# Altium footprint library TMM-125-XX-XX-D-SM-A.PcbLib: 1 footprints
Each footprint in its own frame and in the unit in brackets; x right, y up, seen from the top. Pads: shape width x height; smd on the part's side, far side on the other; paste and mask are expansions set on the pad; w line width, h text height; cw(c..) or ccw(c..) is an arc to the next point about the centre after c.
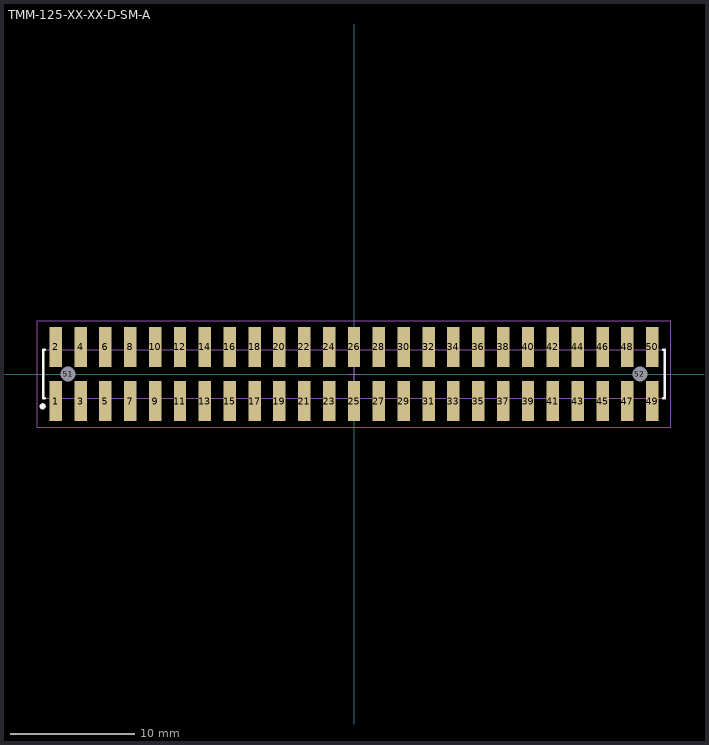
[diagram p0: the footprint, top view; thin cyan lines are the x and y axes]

## TMM-125-XX-XX-D-SM-A [mm] "2.00mm pitch, 50 pin, terminal strip; double row, w/alignment pins, SMT"
height 2.77
pads (52):
  rect 1x3.2 smd mask+0: 1(-24,-2.178) 2(-24,2.178) 3(-22,-2.178) 4(-22,2.178) 5(-20,-2.178) 6(-20,2.178) 7(-18,-2.178) 8(-18,2.178) 9(-16,-2.178) 10(-16,2.178) 11(-14,-2.178) 12(-14,2.178) 13(-12,-2.178) 14(-12,2.178) 15(-10,-2.178) 16(-10,2.178) 17(-8,-2.178) 18(-8,2.178) 19(-6,-2.178) 20(-6,2.178) 21(-4,-2.178) 22(-4,2.178) 23(-2,-2.178) 24(-2,2.178) 25(0,-2.178) 26(0,2.178) 27(2,-2.178) 28(2,2.178) 29(4,-2.178) 30(4,2.178) 31(6,-2.178) 32(6,2.178) 33(8,-2.178) 34(8,2.178) 35(10,-2.178) 36(10,2.178) 37(12,-2.178) 38(12,2.178) 39(14,-2.178) 40(14,2.178) 41(16,-2.178) 42(16,2.178) 43(18,-2.178) 44(18,2.178) 45(20,-2.178) 46(20,2.178) 47(22,-2.178) 48(22,2.178) 49(24,-2.178) 50(24,2.178)
  round 1 hole 1.2 unplated mask+0: 51(-23.006,0) 52(23.006,0)
Top Overlay:
  circle w0.25: c-25.05,-2.6 r0.125
  lines w0.2: -24.9,-1.95 -25,-1.95 -25,1.95 -24.9,1.95 ; 24.9,-1.95 25,-1.95 25,1.95 24.9,1.95
Mechanical 12:
  lines w0.001: -25,-1.95 25,-1.95 25,1.95 -25,1.95 -25,-1.95
Mechanical 13:
  circle w0.1: c-24.126,-2.752 r0.127
  lines w0.1: -25,-1.95 25,-1.95 25,1.95 -25,1.95 -25,-1.95
  text ".Designator" at 0,-0.127 h1.52
Mechanical 15:
  lines w0.05: -0.5,0 0.5,0 ; 0,-0.5 0,0.5 ; -25.5,-4.3 25.5,-4.3 25.5,4.3 -25.5,4.3 -25.5,-4.3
